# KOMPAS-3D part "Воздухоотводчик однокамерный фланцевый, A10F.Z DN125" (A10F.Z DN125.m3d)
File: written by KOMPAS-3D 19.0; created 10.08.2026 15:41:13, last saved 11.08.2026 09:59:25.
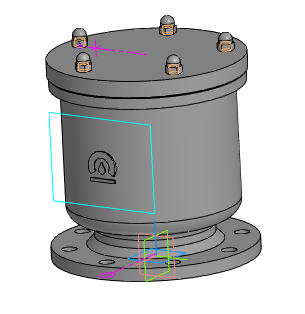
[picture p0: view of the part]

Document properties: Автор: Энергия; Полное имя файла: Z:\3.Личные\kachalov\001_3d для проектировщиков\x.x Тип A10F.Z Воздухоотводчик однокамерный фланцевый\A10F.Z DN125.m3d

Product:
- Part/product: Воздухоотводчик однокамерный фланцевый  | designation A10F.Z DN125
    Масса: 46.0016
  - Component [standard]: Гайка М12-6H (S18) ГОСТ 11860-85  | qty 5  | Масса: 0.02606; Раздел спецификации: Стандартные изделия; Рассекать на разрезах: no; source file: C:\Program Files\ASCON\KOMPAS-3D v19\Libs\PARTLib\DATA\vault\Methods\Kompas\3D\PLib_Blind_Nut_type1_900.m3d
  - Body: Тело 1
      Масса: 45.9495

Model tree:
1. Эскиз:1
2. Элемент вращения:1
     Угол 1 = 360
3. Скругление:1  (with: Элемент вращения:1)
     Радиус = 10
4. Фаска:1  (with: Элемент вращения:1)
     Угол = 45; Длина 1 = 10; Длина 2 = 10
5. Эскиз:2  (with: Элемент вращения:1)
6. Точка:1
     Y = -95; Z = 248; Координата Y = -95; Координата Z = 248
7. Массив по концентрической сетке:1  (with: Элемент вращения:1)  (5 pattern instances)
     Шаг 2 = 360
8. Эскиз:3  (with: Элемент вращения:1)
9. Элемент выдавливания:1  (with: Элемент вращения:1, Массив по концентрической сетке:1, Эскиз:3)  (8 pattern instances)
     Расстояние 2 = 16; N 1 = 1; Шаг 1 = 10; Шаг 2 = 360; Номер 1 = 1
10. Касательная плоскость:1  (with: Элемент вращения:1)
11. Эскиз:4
12. Элемент выдавливания:2  (with: Элемент вращения:1)  (labels: Фаска наружная:1)
     Расстояние 1 = 1; Ориентация = 2

Expressions: Dn/2; D2/2; D/2; B/2; D1/2; H/2; D1-20
Referenced files in C:\Program Files\ASCON\KOMPAS-3D v19\Libs\PARTLib\DATA\vault\Methods\Kompas\3D\: PLib_Blind_Nut_type1_900.m3d
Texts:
  A10F.Z DN125
  Гайка М12-6H (S18) ГОСТ 11860-85 (1)
  foc1
  foc2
